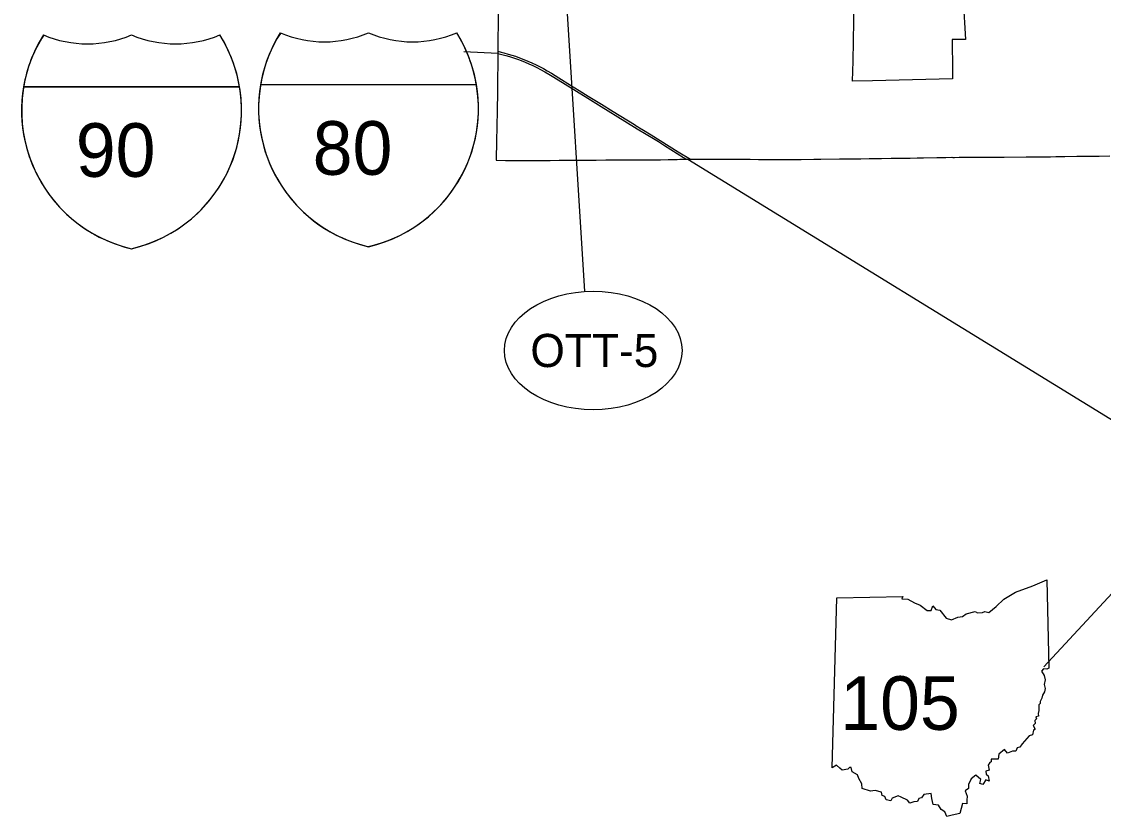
# Model space of a CAD drawing. Extents: x -82 to 873, y 0 to 440.
# Drawn here: x 52.8 to 144.2, y 109.3 to 176.4 of the extents above; entities that cross this region are included whole.
import ezdxf

# ---------------------------------------------------------------- set-up
doc = ezdxf.new("R2010")
doc.units = 0
for name, color, linetype in [('DV_X_Corp_Line', 7, 'Continuous'), ('GM_X_County', 7, 'Continuous'), ('GM_X_Interstate_Route', 7, 'Continuous'), ('PV_P_Text', 7, 'Continuous'), ('SH_Data', 7, 'Continuous')]:
    doc.layers.add(name, color=color, linetype=linetype)

msp = doc.modelspace()

# ---------------------------------------------------------------- linework, layer by layer
at = {"layer": 'DV_X_Corp_Line'}
msp.add_lwpolyline([(132.377, 178.245), (132.574, 174.91), (131.428, 174.923), (131.44, 174.338), (131.462, 172.856), (131.465, 172.419), (131.468, 171.95), (131.467, 171.662), (131.467, 171.596), (124.71, 171.439), (123.031, 171.405), (123.083, 173.099), (123.164, 178.161)], dxfattribs=at)
at = {"layer": 'GM_X_County'}
msp.add_lwpolyline([(93.088, 177.086), (93.075, 175.899), (93.067, 175.281), (93.066, 174.992), (93.062, 174.377), (93.053, 173.922), (93.051, 173.83), (93.051, 173.74), (93.043, 173.099), (93.022, 171.354), (93.018, 170.657), (92.987, 168.718), (92.972, 167.777), (92.95, 166.137), (92.924, 164.968), (92.921, 164.719), (93.704, 164.707), (94.309, 164.707), (95.69, 164.705), (96.461, 164.702), (97.092, 164.706), (97.486, 164.71), (98.224, 164.72), (99.086, 164.722), (99.753, 164.725), (100.438, 164.73), (101.351, 164.736), (102.171, 164.74), (103.019, 164.748), (104.169, 164.759), (104.608, 164.761), (104.762, 164.759), (104.852, 164.753), (104.9, 164.75), (105.069, 164.75), (105.604, 164.757), (106.792, 164.766), (107.455, 164.777), (107.776, 164.78), (108.202, 164.789), (108.436, 164.795), (108.721, 164.801), (108.999, 164.803), (109.105, 164.804), (109.321, 164.806), (109.657, 164.805), (110.301, 164.807), (110.98, 164.806), (111.683, 164.811), (113.313, 164.807), (114.384, 164.8), (115.081, 164.792), (115.646, 164.789), (117.342, 164.793), (118.081, 164.792), (118.159, 164.791), (118.248, 164.789), (118.692, 164.791), (119.761, 164.802), (120.343, 164.807), (121.93, 164.824), (123.125, 164.843), (123.737, 164.849), (124.442, 164.856), (125.466, 164.871), (126.278, 164.882), (127.356, 164.9), (127.879, 164.907), (128.488, 164.917), (129.017, 164.929), (130.14, 164.943), (130.897, 164.957), (131.413, 164.965), (131.491, 164.96), (131.523, 164.958), (131.648, 164.959), (132.03, 164.966), (132.851, 164.975), (133.598, 164.974), (134.889, 164.987), (135.844, 164.99), (137.685, 164.997), (138.829, 165.008), (139.753, 165.015), (140.191, 165.025), (140.957, 165.038), (141.977, 165.055), (142.695, 165.057), (143.359, 165.06), (143.85, 165.07), (144.77, 165.089)], dxfattribs=at)
at = {"layer": 'GM_X_Interstate_Route'}
for p, q in [((93.051, 173.74), (90.187, 173.869)), ((109.105, 164.804), (145.117, 142.669))]:
    msp.add_line(p, q, dxfattribs=at)
for points in [[(93.051, 173.74), (93.738, 173.564), (94.054, 173.475), (94.369, 173.376), (94.719, 173.255), (95.027, 173.14), (95.371, 173.003), (95.674, 172.873), (96.01, 172.718), (96.342, 172.554), (96.671, 172.383), (97.031, 172.185), (97.352, 171.999), (97.773, 171.743), (100.673, 169.949), (101.788, 169.253), (103.782, 168.025), (104.84, 167.376), (106.335, 166.459), (106.617, 166.288), (106.964, 166.067), (107.136, 165.955), (108.75, 164.96), (108.999, 164.803)], [(93.053, 173.922), (93.331, 173.851), (93.567, 173.791), (93.923, 173.693), (94.238, 173.599), (94.55, 173.497), (94.898, 173.374), (95.243, 173.242), (95.585, 173.101), (95.922, 172.952), (96.293, 172.776), (96.623, 172.61), (96.913, 172.455), (97.234, 172.273), (97.587, 172.063), (98.214, 171.673), (99.19, 171.067), (99.926, 170.618), (100.692, 170.14), (101.808, 169.448), (102.786, 168.843), (104.602, 167.724), (104.839, 167.58), (104.848, 167.575), (105.021, 167.466), (105.369, 167.247), (105.998, 166.86), (108.302, 165.437), (109.321, 164.806)], [(139.193, 121.929), (145.336, 128.548)]]:
    msp.add_lwpolyline(points, dxfattribs=at)
at = {"layer": 'PV_P_Text'}
for p, q in [((52.99, 170.929), (71.234, 170.931)), ((71.234, 170.931), (52.99, 170.929)), ((71.234, 170.931), (52.99, 170.929)), ((73.007, 171.101), (91.25, 171.103)), ((91.25, 171.103), (73.007, 171.101)), ((91.25, 171.103), (73.007, 171.101)), ((121.295, 113.391), (121.696, 127.754)), ((121.295, 113.391), (121.696, 127.754))]:
    msp.add_line(p, q, dxfattribs=at)
for points in [[(121.696, 127.754), (127.269, 127.848), (127.182, 127.674), (127.708, 127.638), (128.266, 127.331), (128.738, 127.138), (129.316, 126.681), (129.662, 126.686), (129.808, 127.061), (130.073, 126.772), (130.387, 126.72), (130.93, 126.033), (131.379, 125.884), (131.916, 126.119), (132.318, 126.158), (132.611, 126.391), (133.376, 126.59), (133.589, 126.471), (133.994, 126.495), (134.197, 126.583), (134.551, 126.505), (135.172, 127.027), (135.812, 127.643), (136.796, 128.224), (138.266, 128.774), (139.429, 129.267), (139.597, 121.813)], [(121.696, 127.754), (127.269, 127.848), (127.182, 127.674), (127.708, 127.638), (128.266, 127.331), (128.738, 127.138), (129.316, 126.681), (129.662, 126.686), (129.808, 127.061), (130.073, 126.772), (130.387, 126.72), (130.93, 126.033), (131.379, 125.884), (131.916, 126.119), (132.318, 126.158), (132.611, 126.391), (133.376, 126.59), (133.589, 126.471), (133.994, 126.495), (134.197, 126.583), (134.551, 126.505), (135.172, 127.027), (135.812, 127.643), (136.796, 128.224), (138.266, 128.774), (139.429, 129.267), (139.597, 121.813)], [(139.597, 121.813), (139.426, 121.709), (139.158, 121.758), (138.979, 121.549), (139.201, 121.2), (139.306, 120.832), (139.213, 120.426), (139.305, 120.09), (139.243, 119.81), (139.075, 119.531), (139.017, 119.265), (138.874, 118.985), (138.886, 118.828), (138.75, 118.704), (138.775, 118.237), (138.706, 117.979), (138.73, 117.756), (138.509, 117.698), (138.56, 117.514), (138.419, 117.372), (138.449, 117.127), (138.29, 116.971), (138.445, 116.658), (138.321, 116.559), (138.218, 116.179), (137.935, 116.101), (137.368, 115.406), (137.168, 115.143), (136.943, 115.077), (136.82, 114.807), (136.543, 114.806), (136.124, 114.619), (135.854, 114.941), (135.38, 114.553), (135.325, 114.105), (134.726, 114.12), (134.749, 113.893), (134.615, 113.827), (134.493, 113.6), (134.564, 113.197), (134.284, 113.095), (134.318, 112.86), (134.497, 112.717), (134.577, 112.27), (134.279, 112.361), (134.035, 111.984), (133.783, 112.072), (133.866, 112.392), (133.441, 112.775), (133.039, 112.468), (132.83, 111.977), (132.828, 111.646), (132.528, 111.446), (132.72, 110.979), (132.685, 110.657), (132.691, 110.352), (132.317, 110.363), (132.091, 109.538)], [(139.597, 121.813), (139.426, 121.709), (139.158, 121.758), (138.979, 121.549), (139.201, 121.2), (139.306, 120.832), (139.213, 120.426), (139.305, 120.09), (139.243, 119.81), (139.075, 119.531), (139.017, 119.265), (138.874, 118.985), (138.886, 118.828), (138.75, 118.704), (138.775, 118.237), (138.706, 117.979), (138.73, 117.756), (138.509, 117.698), (138.56, 117.514), (138.419, 117.372), (138.449, 117.127), (138.29, 116.971), (138.445, 116.658), (138.321, 116.559), (138.218, 116.179), (137.935, 116.101), (137.368, 115.406), (137.168, 115.143), (136.943, 115.077), (136.82, 114.807), (136.543, 114.806), (136.124, 114.619), (135.854, 114.941), (135.38, 114.553), (135.325, 114.105), (134.726, 114.12), (134.749, 113.893), (134.615, 113.827), (134.493, 113.6), (134.564, 113.197), (134.284, 113.095), (134.318, 112.86), (134.497, 112.717), (134.577, 112.27), (134.279, 112.361), (134.035, 111.984), (133.783, 112.072), (133.866, 112.392), (133.441, 112.775), (133.039, 112.468), (132.83, 111.977), (132.828, 111.646), (132.528, 111.446), (132.72, 110.979), (132.685, 110.657), (132.691, 110.352), (132.317, 110.363), (132.091, 109.538)], [(132.091, 109.538), (131.44, 109.38), (130.989, 109.286), (130.83, 109.66), (130.507, 109.858), (130.297, 110.235), (129.833, 110.286), (129.723, 110.804), (129.671, 111.224), (129.038, 111.121), (128.864, 110.864), (128.639, 110.795), (128.508, 110.536), (128.202, 110.514), (127.873, 110.392), (127.658, 110.646), (127.119, 110.901), (126.877, 111.032), (126.371, 110.828), (126.262, 110.586), (125.859, 110.693), (125.765, 110.962), (125.521, 111.043), (125.467, 111.329), (124.946, 111.482), (124.547, 111.421), (123.843, 111.651), (123.8, 112.027), (123.561, 112.486), (123.436, 112.805), (122.991, 113.048), (122.901, 113.426), (122.759, 113.415), (122.629, 113.261), (122.135, 113.191), (121.937, 113.346), (121.661, 113.61), (121.295, 113.391)], [(132.091, 109.538), (131.44, 109.38), (130.989, 109.286), (130.83, 109.66), (130.507, 109.858), (130.297, 110.235), (129.833, 110.286), (129.723, 110.804), (129.671, 111.224), (129.038, 111.121), (128.864, 110.864), (128.639, 110.795), (128.508, 110.536), (128.202, 110.514), (127.873, 110.392), (127.658, 110.646), (127.119, 110.901), (126.877, 111.032), (126.371, 110.828), (126.262, 110.586), (125.859, 110.693), (125.765, 110.962), (125.521, 111.043), (125.467, 111.329), (124.946, 111.482), (124.547, 111.421), (123.843, 111.651), (123.8, 112.027), (123.561, 112.486), (123.436, 112.805), (122.991, 113.048), (122.901, 113.426), (122.759, 113.415), (122.629, 113.261), (122.135, 113.191), (121.937, 113.346), (121.661, 113.61), (121.295, 113.391)]]:
    msp.add_lwpolyline(points, dxfattribs=at)
for centre, radius, start, end in [((85.852, 184.292), 9.569, 247.09662, 292.91336), ((85.852, 184.292), 9.569, 247.09662, 292.91336), ((79.43, 169.093), 11.989, 283.01154, 32.18368), ((79.43, 169.093), 11.99, 9.65253, 32.18402), ((64.811, 168.921), 11.99, 147.82661, 256.99913), ((64.061, 169.129), 11.216, 146.65897, 170.76399), ((58.387, 184.118), 9.567, 247.08982, 292.91553), ((58.387, 184.118), 9.567, 247.08982, 292.91553), ((65.836, 184.12), 9.569, 247.09662, 292.91336), ((65.836, 184.12), 9.569, 247.09662, 292.91336), ((59.414, 168.921), 11.989, 283.01154, 32.18368), ((59.414, 168.921), 11.99, 9.65253, 32.18402), ((84.827, 169.093), 11.99, 147.82661, 256.99913), ((84.077, 169.301), 11.216, 146.65897, 170.76399), ((78.403, 184.29), 9.567, 247.08982, 292.91553), ((78.403, 184.29), 9.567, 247.08982, 292.91553), ((64.81, 168.921), 11.989, 170.35636, 257.0017), ((59.439, 168.916), 11.966, 282.77165, 9.69483), ((84.826, 169.093), 11.989, 170.35636, 257.0017), ((79.455, 169.088), 11.966, 282.77165, 9.69483)]:
    msp.add_arc(centre, radius, start, end, dxfattribs=at)
at = {"layer": 'SH_Data'}
msp.add_line((100.412, 153.623), (96.328, 218.587), dxfattribs=at)
msp.add_ellipse((101.116, 148.645), major_axis=(7.5, 0), ratio=0.666667, dxfattribs=at)

# ---------------------------------------------------------------- texts
at = {"layer": 'PV_P_Text'}
for s, p in [('90', (57.395, 163.316)), ('80', (77.411, 163.488)), ('105', (121.984, 116.594))]:
    msp.add_text(s, height=4.5281, rotation=0.005, dxfattribs=at).set_placement(p)
at = {"layer": 'SH_Data'}
msp.add_text('OTT-5', height=2.8, dxfattribs=at).set_placement((95.803, 147.245))

doc.saveas('drawing.dxf')
